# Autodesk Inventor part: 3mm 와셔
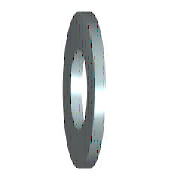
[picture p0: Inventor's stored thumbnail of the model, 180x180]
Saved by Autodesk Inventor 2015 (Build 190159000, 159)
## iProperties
Created: 2012-02
Part Number: 3mm 와셔
Material: 스테인리스강
Description: 평면 와셔 - 대형 시리즈 - 제품 등급 A
Document SubType Name: Modeling
Standard: ISO 7093 A
Designer: mduedu
Standard Revision: First Edition 2000-06-01
Standards Organization: ISO
Language: ko-KR
Size Designation: ST 3 - 140 HV - A
Categories: <MemberInstance><Categories><Category DisplayName="조임쇠" InternalName="e4da775c-781d-43d5-af7c-5136215cf5a6" Mnemonic="FSTN"><Category DisplayName="와셔" InternalN
Density: 8.08 g/cm^3
Appearance: 파란색 - 벽 페인트 - 광택
Mass: 0.359235 g
Surface Area: 1.41811 cm^2
Volume: 0.0444598 cm^3
IsCustomPart: 1
Author: mduedu
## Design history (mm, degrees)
sketch "스케치"
  geometry: C1 r 4.5 at (0, 0); C2 r 1.6 at (0, 0); 1 further point
  constraints: 2 centre point, 2 coincident
  dimensions: "d0" = 3.2 diameter of C2 (= SD1); "d1" = 9 diameter of C1 (= SD2)
extrude "본체" new body sketch "스케치" distance "d2" = 0.8 (= SD); taper "d3" = 0 deg
workaxis "Work Axis1"
workplane "Work Plane1"
sketch "스케치5"
  geometry: 2 further points
  constraints: 1 coincident
body "Solid1"
other parameters: "SD1" = 3.2 [user parameter; used in 1 equation term], "SD2" = 9 [user parameter; used in 1 equation term], "SD" = 0.8 [user parameter; used in 1 equation term], "d4" = 0, "d5" = 0, "d6" = 0, "d7" = 0, "NND" = 3 [user parameter]
